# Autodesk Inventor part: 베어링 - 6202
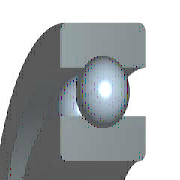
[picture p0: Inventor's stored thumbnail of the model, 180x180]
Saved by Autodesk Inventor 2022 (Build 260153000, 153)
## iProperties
IsCustomPart: 1
Created: 2015-09
Part Number: 베어링 - 6202
Material: 강, 연강
Description: 깊은 그루브 볼 베어링
Document SubType Name: Modeling
Standard: KS B 2023
Designer: mduedu
Standards Organization: KS
Language: ko-KR
Size Designation: 6202 - 15 x 35 x 11
Categories: <MemberInstance><Categories><Category DisplayName="샤프트 부품" InternalName="7f7aeb1f-a693-4053-b835-cee3144e0d98" Mnemonic="SHFT"><Category DisplayName="베어링" Inter
Density: 7.86 g/cm^3
Mass: 45.8725 g
Surface Area: 51.5584 cm^2
Volume: 5.83619 cm^3
Appearance: 노란색
Author: mduedu
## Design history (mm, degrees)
sketch "스케치" dims "d0" = 5.2 (= -0.26 x WD + 0.26 x BD)
  geometry: L1 (2.9, 12.5)-(8.1, 12.5); L2 (5.5, 12.5)-(5.5, 9.9); L3 (5.5, 12.5)-(5.5, 15.1); L4 (3.568, 10.76)-(0, 10.76); L5 (0, 7.5)-(11, 7.5); L6 (3.568, 14.24)-(0, 14.24); L7 (0, 17.5)-(11, 17.5); L8 (11, 7.5)-(11, 10.76); L9 (7.432, 10.76)-(11, 10.76); L10 (7.432, 14.24)-(11, 14.24); L11 (11, 17.5)-(11, 14.24); L12 (-1.4, 0)-(8.4, 0) reference; L13 (0, -0.3)-(0, 5.3) reference
  constraints: 22 end point, 4 point on line, 2 collinear, 2 perpendicular, 2 symmetric about line, 1 midpoint, 1 parallel, 14 other
  dimensions: "d9" = 15 diameter of L5 L12 (= WD); "d11" = 35 diameter of L7 L12 (= BD); "d12" = 11 distance between parallel lines of L8 L13 (= KB); "d13" = 21.52 diameter of L9 L12 (= 0.326 x BD + 0.674 x WD)
revolve "본체" stored, may be unused: angle "d6" = 90 deg
revolve "볼" stored, may be unused: angle "d7" = 90 deg
pattern_circular "IDS_ARRAYBALL[SIMPL:T]" dims angle "d3" = 360 deg
body "Solid1"
fillet "모깎기1" dims "d1" = 0.6 (= KRS)
other parameters: "WD" = 15 [user parameter; used in 5 equation terms], "BD" = 35 [user parameter; used in 5 equation terms], "KB" = 11 [user parameter; used in 1 equation term], "KRS" = 0.6 [user parameter; used in 1 equation term], "d4" = 0, "d5" = 0, "d8" = 0, "d14" = 0, "d15" = 0, "BBA" = 0 [user parameter], "BC0" = 3750000 [user parameter], "BC" = 7800000 [user parameter], "BR" = 17.5 (= 0.5 x BD) [user parameter], "WR" = 7.5 (= 0.5 x WD) [user parameter]
